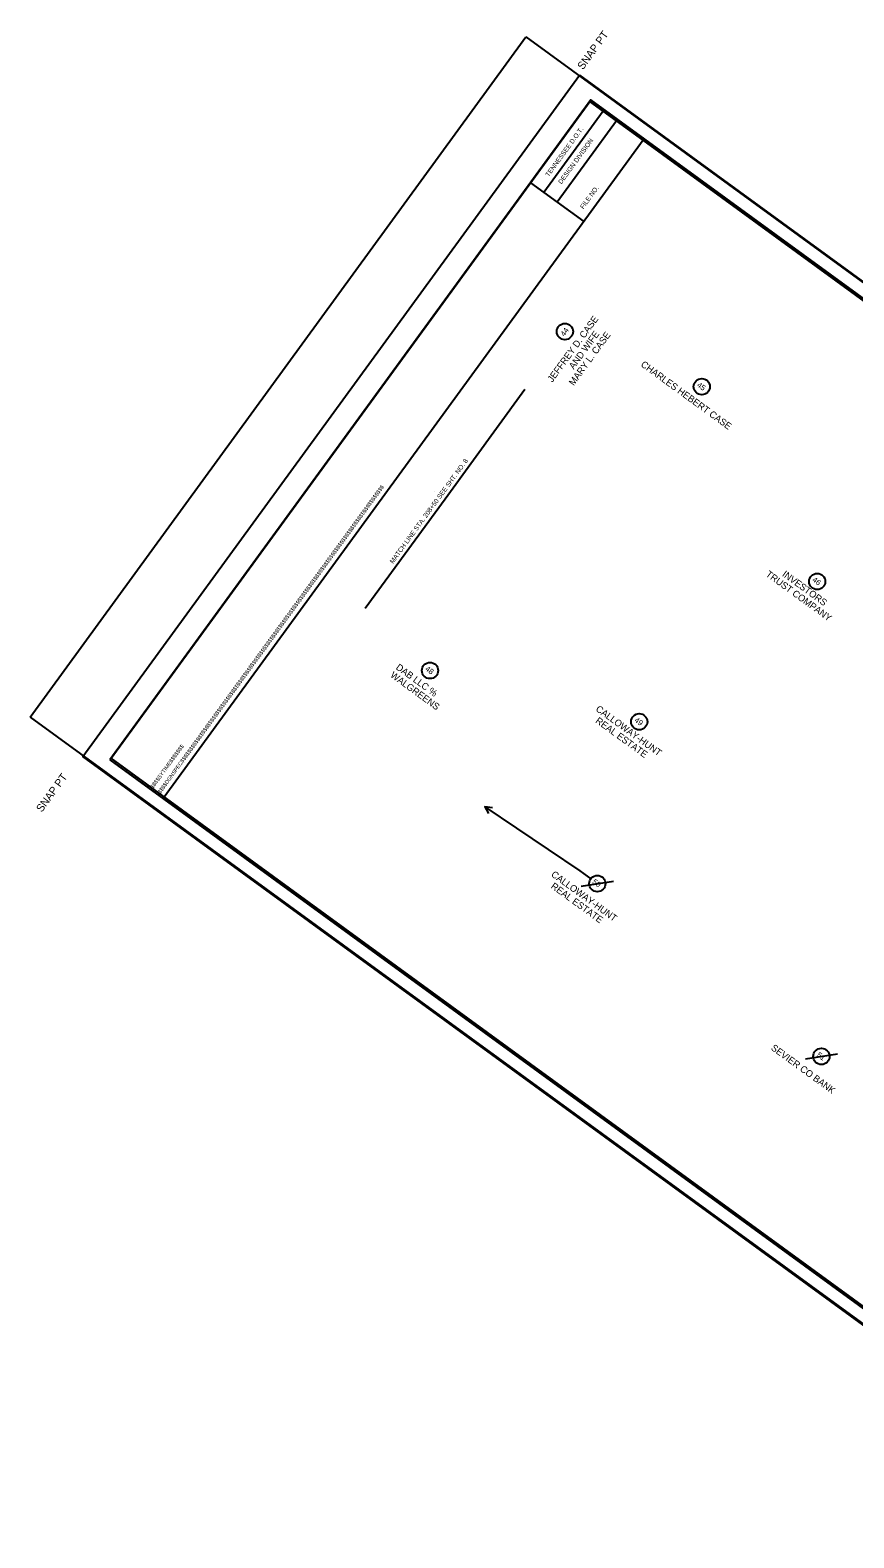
# Model space of a CAD drawing. Extents: x 2632015 to 2634135, y 566161 to 568172.
# Drawn here: x 2632015 to 2633079, y 566225 to 568172 of the extents above; entities that cross this region are included whole.
import ezdxf

# ---------------------------------------------------------------- set-up
doc = ezdxf.new("R2010")
doc.units = 0
for name, color, linetype in [('DESIGN - CENTERLINE - Proposed Text', 7, 'Continuous'), ('DESIGN - SCRATCH - User 1', 7, 'Continuous'), ('DESIGN - SHEET - Corner Text', 7, 'Continuous'), ('DESIGN - SHEET - Light Grid', 7, 'Continuous'), ('DESIGN - SHEET - Linework', 7, 'Continuous'), ('DESIGN - SHEET - Plot Shape', 7, 'Continuous'), ('SURVEY - PROPERTY - Owners', 7, 'Continuous'), ('SURVEY - PROPERTY - Tract Numbers', 7, 'Continuous')]:
    doc.layers.add(name, color=color, linetype=linetype)

msp = doc.modelspace()

# ---------------------------------------------------------------- linework, layer by layer
at = {"layer": 'DESIGN - CENTERLINE - Proposed Text'}
msp.add_lwpolyline([(2632448.1, 567425.5), (2632551.2, 567566.9), (2632654.3, 567708.4)], dxfattribs=at)
at = {"layer": 'DESIGN - SCRATCH - User 1'}
msp.add_line((2632538.2, 567576.4), (2632538.2, 567576.4), dxfattribs=at)
at = {"layer": 'DESIGN - SHEET - Light Grid'}
msp.add_lwpolyline([(2632118.4, 567229.6), (2633464, 566249), (2634085.3, 567101.7), (2632739.7, 568082.2)], close=True, dxfattribs=at)
at = {"layer": 'DESIGN - SHEET - Linework'}
for p, q in [((2632015.3, 567284.7), (2632655.7, 568163.5)), ((2632655.7, 568163.5), (2634110.4, 567103.4)), ((2632755.4, 568067.7), (2632678.9, 567962.7)), ((2632772.6, 568055.2), (2632696.1, 567950.2)), ((2632015.3, 567284.7), (2633470, 566224.6))]:
    msp.add_line(p, q, dxfattribs=at)
for points in [[(2632807, 568030.1), (2632738.3, 568080.2), (2632661.7, 567975.2), (2632730.5, 567925.2)], [(2632807, 568030.1), (2632188.6, 567181.6), (2633460.8, 566254.4), (2634079.2, 567103), (2632807, 568030.1)]]:
    msp.add_lwpolyline(points, dxfattribs=at)
at = {"layer": 'DESIGN - SHEET - Plot Shape'}
for points in [[(2632724.9, 568114.3), (2634098.8, 567113.1), (2633457.2, 566232.7), (2632083.3, 567233.9)], [(2632738.3, 568080.2), (2634079.2, 567103), (2633460.8, 566254.4), (2632119.9, 567231.6)]]:
    msp.add_lwpolyline(points, close=True, dxfattribs=at)
at = {"layer": 'SURVEY - PROPERTY - Tract Numbers'}
for p, q in [((2632727.1, 567066.6), (2632768.6, 567073.1)), ((2633016.6, 566843.2), (2633058, 566849.7))]:
    msp.add_line(p, q, dxfattribs=at)
for points in [[(2632612.3, 567167.6), (2632602.6, 567168.9), (2632607.5, 567160.4)], [(2632602.6, 567168.9), (2632725.3, 567086.3)], [(2632725.3, 567086.3), (2632739.4, 567076)]]:
    msp.add_lwpolyline(points, dxfattribs=at)
for centre in [(2632706, 567782.9), (2632882.8, 567711.7), (2633031.9, 567460), (2632531.8, 567345), (2632802, 567278.8), (2632747.9, 567069.8), (2633037.3, 566846.5)]:
    msp.add_circle(centre, 10.5, dxfattribs=at)

# ---------------------------------------------------------------- texts
at = {"layer": 'DESIGN - CENTERLINE - Proposed Text'}
msp.add_text('MATCH LINE STA. 208+50 SEE SHT. NO. 8', height=6, rotation=53.918, dxfattribs=at).set_placement((2632484.1, 567482.5))
at = {"layer": 'DESIGN - SHEET - Corner Text'}
for s, height, p in [('  SNAP PT', 10, (2632724.9, 568114.3)), ('TENNESSEE D.O.T.', 6, (2632685.2, 567982.3)), ('DESIGN DIVISION', 6, (2632701.6, 567972.8)), ('FILE NO.', 6, (2632729.9, 567940.6)), ('$$$$DGNSPEC$$$$$$$$$$$$$$$$$$$$$$$$$$$$$$$$$$$$$$$$$$$$$$$$$$$$$$$$$$$$$$$$$$$$$$$$$$$$$$$$$$$$$$$$$$$$$$$$$$$$$$$$$$$$$$$$$$$', 5.0001, (2632183.5, 567185.3)), ('$$$$SYTIME$$$$$$$', 5, (2632174.1, 567192.1)), ('SNAP PT  ', 10, (2632030.3, 567161.2))]:
    msp.add_text(s, height=height, rotation=53.918, dxfattribs=at).set_placement(p)
at = {"layer": 'SURVEY - PROPERTY - Owners'}
for s, rotation, p in [('JEFFREY D. CASE', 53.918, (2632689.7, 567716.6)), ('MARY L. CASE', 53.918, (2632717.4, 567712.3)), ('AND WIFE', 53.918, (2632717.4, 567733.4)), ('CHARLES HEBERT CASE', 323.918, (2632803.2, 567738.7)), ('TRUST COMPANY', 323.918, (2632964.7, 567467.7)), ('INVESTORS', 323.918, (2632985.9, 567467.7)), ('DAB LLC %', 323.918, (2632486.9, 567347.4)), ('WALGREENS', 323.918, (2632479.7, 567337.3)), ('CALLOWAY-HUNT', 323.918, (2632745, 567293.6)), ('REAL ESTATE', 323.918, (2632744.7, 567278.4)), ('CALLOWAY-HUNT', 323.918, (2632687.4, 567079.9)), ('REAL ESTATE', 323.918, (2632687.1, 567064.7)), ('SEVIER CO BANK', 323.918, (2632971.4, 566855.8))]:
    msp.add_text(s, height=8.75, rotation=rotation, dxfattribs=at).set_placement(p)
at = {"layer": 'SURVEY - PROPERTY - Tract Numbers'}
for s, rotation, p in [('44', 53.918, (2632705.3, 567776)), ('45', 323.918, (2632875.9, 567712.4)), ('46', 323.918, (2633024.8, 567460.8)), ('48', 323.918, (2632524.8, 567345.8)), ('49', 323.918, (2632795.1, 567279.5)), ('50', 323.918, (2632740.7, 567070.7)), ('51', 323.918, (2633030.6, 566847))]:
    msp.add_text(s, height=7, rotation=rotation, dxfattribs=at).set_placement(p)

doc.saveas('drawing.dxf')
